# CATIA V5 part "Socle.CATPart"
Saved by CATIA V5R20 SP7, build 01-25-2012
Part number: Socle
Bounding box of the stored display mesh (mm): x -55 to 45, y -90 to 90, z 0 to 170
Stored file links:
  J:\ACHTUNG2\Socle.CATPart
  J:\ACHTUNG2\cmilovidof.CATProduct
  J:\ACHTUNG2\Levier1.CATPart
  J:\ACHTUNG2\Patin3.CATPart
  J:\ACHTUNG2\Equerre7.CATPart
  J:\ACHTUNG2\Equerre6.CATPart
  J:\ACHTUNG2\Patin2.CATPart
  J:\ACHTUNG\IAO non optimisé fini et qui marche à rendre\RouePoulie8.CATPart
  J:\ACHTUNG2\skl_Equerre6.CATPart
  J:\ACHTUNG2\skl_Bielle4.CATPart
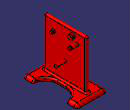
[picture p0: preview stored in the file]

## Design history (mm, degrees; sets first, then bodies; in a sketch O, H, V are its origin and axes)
External parameters (linked from other documents)
  External.diam_roue = 64 mm
Set1
  Plane1: linked copy from another document
  Line1 "Axe_LevierBati": linked copy from another document
  Plane2: linked copy from another document
  Line2 "Axe_Equerre7Socle": linked copy from another document
  Line3 "Axe_Equerre6Socle": linked copy from another document
  Plane3: linked copy from another document
  Line4 "Axe_SocleRoue8": linked copy from another document
  Line5: linked copy from another document
  Line6: linked copy from another document
Body1 (main body)
  Sketch1 on Plane1, origin (-5, 0, 0), H (0, 1, 0), V (0, 0, 1)
    point P1 (70, 0)
    line L1 (70, 0) -> (-70, 0)
    line L2 (-70, 0) -> (-70, 170)
    line L3 (-70, 170) -> (70, 170)
    line L4 (70, 170) -> (70, 0)
    distance L4 V = 70 {= 70*External.diam_roue /64}
    length L4 = 170 {= 170*External.diam_roue /64}
    coincidence: P1 H
    horizontal: L1 H, L3 H
    vertical: L2 V, L4 V
    symmetry: L4 L2 V
  Pad1: profile Sketch1, direction (-1, 0, 0), length 10
  Sketch2 on start face of Pad1, origin (-5, 0, 0), H (0, 1, 0), V (0, 0, 1)
    circle A1 centre (25, 152) radius 8
    reference projected point E1 (25, 152) from Line1
    circle A2 centre (-38.0408, 134.3395) radius 6
    reference projected point E2 (-38.0408, 134.3395) from Line6
    radius A1 = 8 {= 8*External.diam_roue /64}
    radius A2 = 6 {= 6*External.diam_roue /64}
    concentricity: A1 E1, A2 E2
  Pad2: profile Sketch2, direction (1, 0, 0), up to yz-plane
  Sketch3 on end face of Pad2, origin (0, 0, 0), H (0, 1, 0), V (0, 0, 1)
    circle A1 centre (25, 152) radius 6
    reference projected point E1 (25, 152) from Line1
    radius A1 = 6 {= 6*External.diam_roue /64}
    concentricity: A1 E1
  Pad3: profile Sketch3, direction (1, 0, 0), up to Plane2
  Sketch4 on end face of Pad2, origin (0, 0, 0), H (0, 1, 0), V (0, 0, 1)
    circle A1 centre (-38.0408, 134.3395) radius 4
    reference projected point E1 (-38.0408, 134.3395) from Line6
    radius A1 = 4 {= 4*External.diam_roue /64}
    concentricity: A1 E1
  Pad4: profile Sketch4, direction (1, 0, 0), up to Plane2
  Sketch5 on start face of Pad1, origin (-5, 0, 0), H (0, 1, 0), V (0, 0, 1)
    circle A1 centre (38.0408, 134.3395) radius 6
    reference projected point E1 (38.0408, 134.3395) from Line5
    radius A1 = 6 {= 6*External.diam_roue /64}
    concentricity: E1 A1
  Pad5: profile Sketch5, direction (1, 0, 0), up to Plane3
  Sketch6 on end face of Pad5, origin (15, 0, 0), H (0, 1, 0), V (0, 0, 1)
    circle A1 centre (38.0408, 134.3395) radius 4
    reference projected point E1 (38.0408, 134.3395) from Line5
    radius A1 = 4 {= 4*External.diam_roue /64}
    concentricity: E1 A1
  Pad6: profile Sketch6, direction (1, 0, 0), length 5
  Sketch7 on start face of Pad1, origin (-5, 0, 0), H (0, 1, 0), V (0, 0, 1)
    circle A1 centre (0, 68) radius 5
    reference projected point E1 (0, 68) from Line4
    radius A1 = 5 {= 5*External.diam_roue /64}
    concentricity: A1 E1
  Pad7: profile Sketch7, direction (1, 0, 0), length 30
  Sketch8 on start face of Pad1, origin (-5, 0, 0), H (0, 1, 0), V (0, 0, 1)
    line L1 (90, 10) -> (-90, 10)
    line L2 (-90, 10) -> (-90, 0)
    line L3 (-90, 0) -> (90, 0)
    line L4 (90, 0) -> (90, 10)
    reference projected line E1 (-70, 0) -> (70, 0) from edge [face of Pad1 from Sketch1.L1 | start face of Pad1]
    distance L1 L3 = 10 {= 10*External.diam_roue /64}
    distance L2 V = 90 {= 90*External.diam_roue /64}
    horizontal: L1 H, L3 H
    vertical: L2 V, L4 V
    coincidence: E1 L3
    symmetry: L4 L2 V
  Pad8: profile Sketch8, direction (-1, 0, 0), length 50, mirrored extent
  Fillet1: radius 10, on edge [face of Pad8 from Sketch8.L1 | face of Pad8 from Sketch8.L2]; edge [face of Pad8 from Sketch8.L1 | start face of Pad8]; edge [end face of Pad8 | face of Pad8 from Sketch8.L1]; edge [face of Pad8 from Sketch8.L2 | start face of Pad8]; edge [end face of Pad8 | face of Pad8 from Sketch8.L2]; edge [face of Pad8 from Sketch8.L4 | face of Pad8 from Sketch8.L1]; edge [end face of Pad8 | face of Pad8 from Sketch8.L4]; edge [face of Pad8 from Sketch8.L4 | start face of Pad8]
  Sketch9 on face of Pad8, origin (0, 0, 0), H (1, 0, 0), V (0, -1, 0)
    line L1 (5, -15) -> (5, 15)
    arc A1 centre (45, 15) radius 40 from (45, 55) to (5, 15) ccw
    arc A2 centre (45, -15) radius 40 from (5, -15) to (45, -55) ccw
    line L2 (45, 55) -> (45, -55)
    reference projected line E1 (45, -80) -> (45, 80) from edge [face of Fillet1 | face of Pad8]
    length L1 = 30
    radius A2 = 40
    distance L1 L2 = 40
    vertical: L1 V, L2 V
    tangency: A1 L1, A2 L1
    symmetry: A1 A2 H
    coincidence: L2 E1
  Pocket1: profile Sketch9, direction (0, 0, 1), length 50
  Fillet2: radius 5, on edge [face of Fillet1 | face of Pocket1 from Sketch9.A1]; edge [face of Pocket1 from Sketch9.A2 | face of Fillet1]
  Sketch10 on start face of Pad1, origin (-5, 0, 0), H (0, 1, 0), V (0, 0, 1)
    point P1 (70, 0)
    line L1 (70, 0) -> (-70, 0)
    line L2 (-70, 0) -> (-70, 170)
    line L3 (-70, 170) -> (70, 170)
    line L4 (70, 170) -> (70, 0)
    distance L4 V = 70 {= 70*External.diam_roue /64}
    length L4 = 170 {= 170*External.diam_roue /64}
    coincidence: P1 H
    horizontal: L1 H, L3 H
    vertical: L2 V, L4 V
    symmetry: L4 L2 V
  Pad9: profile Sketch10, direction (-1, 0, 0), length 10
  Fillet3: radius 5, on edge [face of Pad8 from Sketch8.L1 | face of Pad9] (x2); edge [face of Pad9 | face of Pad9] (x8); face of Pad9; edge [face of Pad9 | face of Pad8 from Sketch8.L1] (x2)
